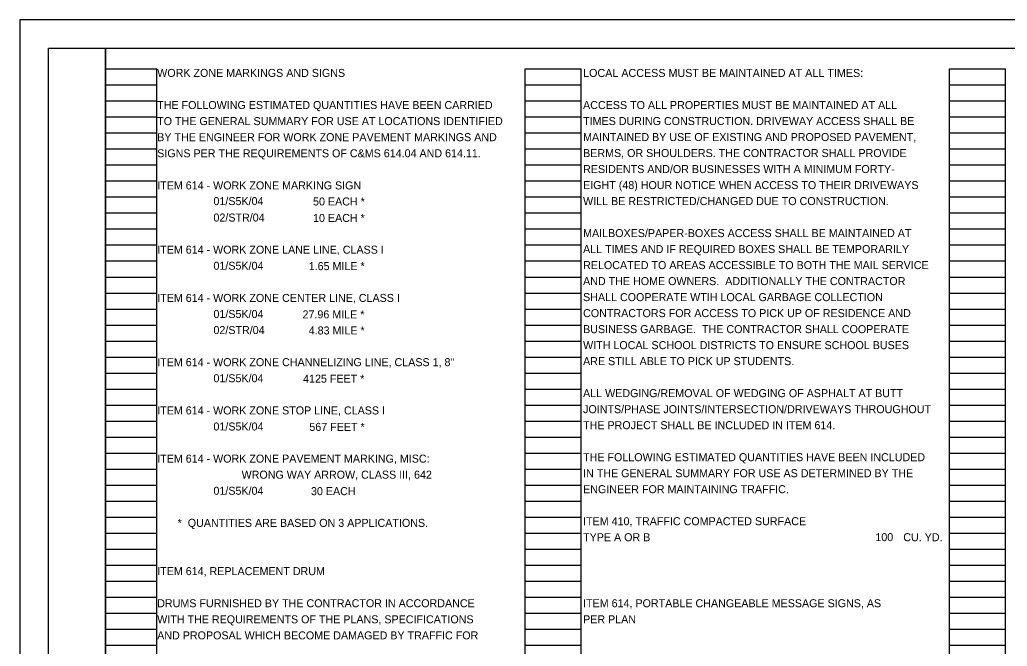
# Model space of a CAD drawing. Extents: x 0 to 34, y 0 to 22.
# Drawn here: x 0 to 17.27, y 11.04 to 22 of the extents above; entities that cross this region are included whole.
import ezdxf

# ---------------------------------------------------------------- set-up
doc = ezdxf.new("R2010")
doc.units = 0
for name, color, linetype in [('SH_Border', 7, 'Continuous'), ('SH_Cut_Line', 7, 'Continuous'), ('SH_Data', 7, 'Continuous'), ('SH_Text', 7, 'Continuous'), ('TX_P_1', 7, 'Continuous')]:
    doc.layers.add(name, color=color, linetype=linetype)

msp = doc.modelspace()

# ---------------------------------------------------------------- linework, layer by layer
at = {"layer": 'SH_Border'}
for points in [[(0.5, 21.5), (1.5, 21.5), (1.5, 0.5), (0.5, 0.5)], [(1.5, 21.5), (33.5, 21.5), (33.5, 0.5), (1.5, 0.5)]]:
    msp.add_lwpolyline(points, close=True, dxfattribs=at)
at = {"layer": 'SH_Cut_Line'}
msp.add_lwpolyline([(0, 0), (34, 0), (34, 22), (0, 22)], close=True, dxfattribs=at)
at = {"layer": 'SH_Data'}
for p, q in [((1.5, 0.98), (1.5, 21.14)), ((1.5, 21.14), (2.4, 21.14)), ((2.4, 0.98), (2.4, 21.14)), ((8.84, 0.98), (8.84, 21.14)), ((8.84, 21.14), (9.82, 21.14)), ((9.82, 0.98), (9.82, 21.14)), ((16.26, 0.98), (16.26, 21.14)), ((16.26, 21.14), (17.24, 21.14)), ((17.24, 0.98), (17.24, 21.14)), ((1.5, 20.86), (2.4, 20.86)), ((8.84, 20.86), (9.82, 20.86)), ((16.26, 20.86), (17.24, 20.86)), ((1.5, 20.58), (2.4, 20.58)), ((8.84, 20.58), (9.82, 20.58)), ((16.26, 20.58), (17.24, 20.58)), ((1.5, 20.3), (2.4, 20.3)), ((8.84, 20.3), (9.82, 20.3)), ((16.26, 20.3), (17.24, 20.3)), ((1.5, 20.02), (2.4, 20.02)), ((8.84, 20.02), (9.82, 20.02)), ((16.26, 20.02), (17.24, 20.02)), ((1.5, 19.74), (2.4, 19.74)), ((8.84, 19.74), (9.82, 19.74)), ((16.26, 19.74), (17.24, 19.74)), ((1.5, 19.46), (2.4, 19.46)), ((8.84, 19.46), (9.82, 19.46)), ((16.26, 19.46), (17.24, 19.46)), ((1.5, 19.18), (2.4, 19.18)), ((8.84, 19.18), (9.82, 19.18)), ((16.26, 19.18), (17.24, 19.18)), ((1.5, 18.9), (2.4, 18.9)), ((8.84, 18.9), (9.82, 18.9)), ((16.26, 18.9), (17.24, 18.9)), ((1.5, 18.62), (2.4, 18.62)), ((8.84, 18.62), (9.82, 18.62)), ((16.26, 18.62), (17.24, 18.62)), ((1.5, 18.34), (2.4, 18.34)), ((8.84, 18.34), (9.82, 18.34)), ((16.26, 18.34), (17.24, 18.34)), ((1.5, 18.06), (2.4, 18.06)), ((8.84, 18.06), (9.82, 18.06)), ((16.26, 18.06), (17.24, 18.06)), ((1.5, 17.78), (2.4, 17.78)), ((8.84, 17.78), (9.82, 17.78)), ((16.26, 17.78), (17.24, 17.78)), ((1.5, 17.5), (2.4, 17.5)), ((8.84, 17.5), (9.82, 17.5)), ((16.26, 17.5), (17.24, 17.5)), ((1.5, 17.22), (2.4, 17.22)), ((8.84, 17.22), (9.82, 17.22)), ((16.26, 17.22), (17.24, 17.22)), ((1.5, 16.94), (2.4, 16.94)), ((8.84, 16.94), (9.82, 16.94)), ((16.26, 16.94), (17.24, 16.94)), ((1.5, 16.66), (2.4, 16.66)), ((8.84, 16.66), (9.82, 16.66)), ((16.26, 16.66), (17.24, 16.66)), ((1.5, 16.38), (2.4, 16.38)), ((8.84, 16.38), (9.82, 16.38)), ((16.26, 16.38), (17.24, 16.38)), ((1.5, 16.1), (2.4, 16.1)), ((8.84, 16.1), (9.82, 16.1)), ((16.26, 16.1), (17.24, 16.1)), ((1.5, 15.82), (2.4, 15.82)), ((8.84, 15.82), (9.82, 15.82)), ((16.26, 15.82), (17.24, 15.82)), ((1.5, 15.54), (2.4, 15.54)), ((8.84, 15.54), (9.82, 15.54)), ((16.26, 15.54), (17.24, 15.54)), ((1.5, 15.26), (2.4, 15.26)), ((8.84, 15.26), (9.82, 15.26)), ((16.26, 15.26), (17.24, 15.26)), ((1.5, 14.98), (2.4, 14.98)), ((8.84, 14.98), (9.82, 14.98)), ((16.26, 14.98), (17.24, 14.98)), ((1.5, 14.7), (2.4, 14.7)), ((8.84, 14.7), (9.82, 14.7)), ((16.26, 14.7), (17.24, 14.7)), ((1.5, 14.42), (2.4, 14.42)), ((8.84, 14.42), (9.82, 14.42)), ((16.26, 14.42), (17.24, 14.42)), ((1.5, 14.14), (2.4, 14.14)), ((8.84, 14.14), (9.82, 14.14)), ((16.26, 14.14), (17.24, 14.14)), ((1.5, 13.86), (2.4, 13.86)), ((8.84, 13.86), (9.82, 13.86)), ((16.26, 13.86), (17.24, 13.86)), ((1.5, 13.58), (2.4, 13.58)), ((8.84, 13.58), (9.82, 13.58)), ((16.26, 13.58), (17.24, 13.58)), ((1.5, 13.3), (2.4, 13.3)), ((8.84, 13.3), (9.82, 13.3)), ((16.26, 13.3), (17.24, 13.3)), ((1.5, 13.02), (2.4, 13.02)), ((8.84, 13.02), (9.82, 13.02)), ((16.26, 13.02), (17.24, 13.02)), ((1.5, 12.74), (2.4, 12.74)), ((8.84, 12.74), (9.82, 12.74)), ((16.26, 12.74), (17.24, 12.74)), ((1.5, 12.46), (2.4, 12.46)), ((8.84, 12.46), (9.82, 12.46)), ((16.26, 12.46), (17.24, 12.46)), ((1.5, 12.18), (2.4, 12.18)), ((8.84, 12.18), (9.82, 12.18)), ((16.26, 12.18), (17.24, 12.18)), ((1.5, 11.9), (2.4, 11.9)), ((8.84, 11.9), (9.82, 11.9)), ((16.26, 11.9), (17.24, 11.9)), ((1.5, 11.62), (2.4, 11.62)), ((8.84, 11.62), (9.82, 11.62)), ((16.26, 11.62), (17.24, 11.62)), ((1.5, 11.34), (2.4, 11.34)), ((8.84, 11.34), (9.82, 11.34)), ((16.26, 11.34), (17.24, 11.34)), ((1.5, 11.06), (2.4, 11.06)), ((8.84, 11.06), (9.82, 11.06)), ((16.26, 11.06), (17.24, 11.06))]:
    msp.add_line(p, q, dxfattribs=at)

# ---------------------------------------------------------------- texts
at = {"layer": 'SH_Border'}
for s, height, p in [('LOCAL ACCESS MUST BE MAINTAINED AT ALL TIMES:', 0.14056, (9.853, 20.999)), ('ACCESS TO ALL PROPERTIES MUST BE MAINTAINED AT ALL', 0.14, (9.853, 20.438)), ('TIMES DURING CONSTRUCTION. DRIVEWAY ACCESS SHALL BE', 0.14, (9.853, 20.158)), ('MAINTAINED BY USE OF EXISTING AND PROPOSED PAVEMENT,', 0.14, (9.853, 19.878)), ('BERMS, OR SHOULDERS. THE CONTRACTOR SHALL PROVIDE', 0.14, (9.853, 19.598)), ('RESIDENTS AND/OR BUSINESSES WITH A MINIMUM FORTY-', 0.14, (9.853, 19.318)), ('EIGHT (48) HOUR NOTICE WHEN ACCESS TO THEIR DRIVEWAYS', 0.14, (9.853, 19.038)), ('WILL BE RESTRICTED/CHANGED DUE TO CONSTRUCTION.', 0.14, (9.853, 18.758)), ('MAILBOXES/PAPER-BOXES ACCESS SHALL BE MAINTAINED AT', 0.14, (9.853, 18.198)), ('ALL TIMES AND IF REQUIRED BOXES SHALL BE TEMPORARILY', 0.14, (9.853, 17.918)), ('RELOCATED TO AREAS ACCESSIBLE TO BOTH THE MAIL SERVICE', 0.14, (9.853, 17.638)), ('AND THE HOME OWNERS.  ADDITIONALLY THE CONTRACTOR', 0.14, (9.853, 17.358)), ('SHALL COOPERATE WTIH LOCAL GARBAGE COLLECTION', 0.14, (9.853, 17.078)), ('CONTRACTORS FOR ACCESS TO PICK UP OF RESIDENCE AND', 0.14, (9.853, 16.798)), ('BUSINESS GARBAGE.  THE CONTRACTOR SHALL COOPERATE', 0.14, (9.853, 16.518)), ('WITH LOCAL SCHOOL DISTRICTS TO ENSURE SCHOOL BUSES', 0.14, (9.853, 16.238)), ('ARE STILL ABLE TO PICK UP STUDENTS.', 0.14, (9.853, 15.958)), ('ALL WEDGING/REMOVAL OF WEDGING OF ASPHALT AT BUTT', 0.14, (9.853, 15.398)), ('JOINTS/PHASE JOINTS/INTERSECTION/DRIVEWAYS THROUGHOUT', 0.14, (9.853, 15.118)), ('THE PROJECT SHALL BE INCLUDED IN ITEM 614.', 0.14, (9.853, 14.838)), ('THE FOLLOWING ESTIMATED QUANTITIES HAVE BEEN INCLUDED', 0.14, (9.853, 14.278)), ('IN THE GENERAL SUMMARY FOR USE AS DETERMINED BY THE', 0.14, (9.853, 13.998)), ('ENGINEER FOR MAINTAINING TRAFFIC.', 0.14, (9.853, 13.718)), ('ITEM 410, TRAFFIC COMPACTED SURFACE', 0.14, (9.853, 13.158)), ('TYPE A OR B', 0.14, (9.853, 12.878)), ('100', 0.14, (14.965, 12.88)), ('CU. YD.', 0.14, (15.453, 12.878))]:
    msp.add_text(s, height=height, dxfattribs=at).set_placement(p)
at = {"layer": 'SH_Text'}
for s, p in [('ITEM 614, PORTABLE CHANGEABLE MESSAGE SIGNS, AS', (9.853, 11.723)), ('PER PLAN', (9.853, 11.442))]:
    msp.add_text(s, height=0.14, dxfattribs=at).set_placement(p)
at = {"layer": 'TX_P_1'}
for s, p in [('WORK ZONE MARKINGS AND SIGNS', (2.404, 21)), ('THE FOLLOWING ESTIMATED QUANTITIES HAVE BEEN CARRIED', (2.404, 20.438)), ('TO THE GENERAL SUMMARY FOR USE AT LOCATIONS IDENTIFIED', (2.404, 20.157)), ('BY THE ENGINEER FOR WORK ZONE PAVEMENT MARKINGS AND', (2.404, 19.876)), ('SIGNS PER THE REQUIREMENTS OF C&MS 614.04 AND 614.11.', (2.404, 19.594)), ('ITEM 614 - WORK ZONE MARKING SIGN', (2.404, 19.032)), ('01/S5K/04', (3.388, 18.758)), ('50 EACH *', (5.13, 18.751)), ('02/STR/04', (3.388, 18.47)), ('10 EACH *', (5.13, 18.463)), ('ITEM 614 - WORK ZONE LANE LINE, CLASS I', (2.404, 17.908)), ('01/S5K/04', (3.388, 17.627)), ('1.65 MILE *', (5.054, 17.62)), ('ITEM 614 - WORK ZONE CENTER LINE, CLASS I', (2.404, 17.064)), ('01/S5K/04', (3.388, 16.783)), ('27.96 MILE *', (4.946, 16.776)), ('02/STR/04', (3.388, 16.502)), ('4.83 MILE *', (5.054, 16.495)), ('ITEM 614 - WORK ZONE CHANNELIZING LINE, CLASS 1, 8"', (2.404, 15.94)), ('01/S5K/04', (3.388, 15.659)), ('4125 FEET *', (4.956, 15.652)), ('ITEM 614 - WORK ZONE STOP LINE, CLASS I', (2.404, 15.096)), ('01/S5K/04', (3.388, 14.815)), ('567 FEET *', (5.065, 14.808)), ('ITEM 614 - WORK ZONE PAVEMENT MARKING, MISC: ', (2.404, 14.253)), ('WRONG WAY ARROW, CLASS III, 642', (3.88, 13.972)), ('01/S5K/04', (3.388, 13.691)), ('30 EACH', (5.094, 13.684)), ('*  QUANTITIES ARE BASED ON 3 APPLICATIONS.', (2.762, 13.129)), ('ITEM 614, REPLACEMENT DRUM', (2.404, 12.285)), ('DRUMS FURNISHED BY THE CONTRACTOR IN ACCORDANCE', (2.404, 11.723)), ('WITH THE REQUIREMENTS OF THE PLANS, SPECIFICATIONS', (2.404, 11.442)), ('AND PROPOSAL WHICH BECOME DAMAGED BY TRAFFIC FOR', (2.404, 11.161))]:
    msp.add_text(s, height=0.14, dxfattribs=at).set_placement(p)

doc.saveas('drawing.dxf')
